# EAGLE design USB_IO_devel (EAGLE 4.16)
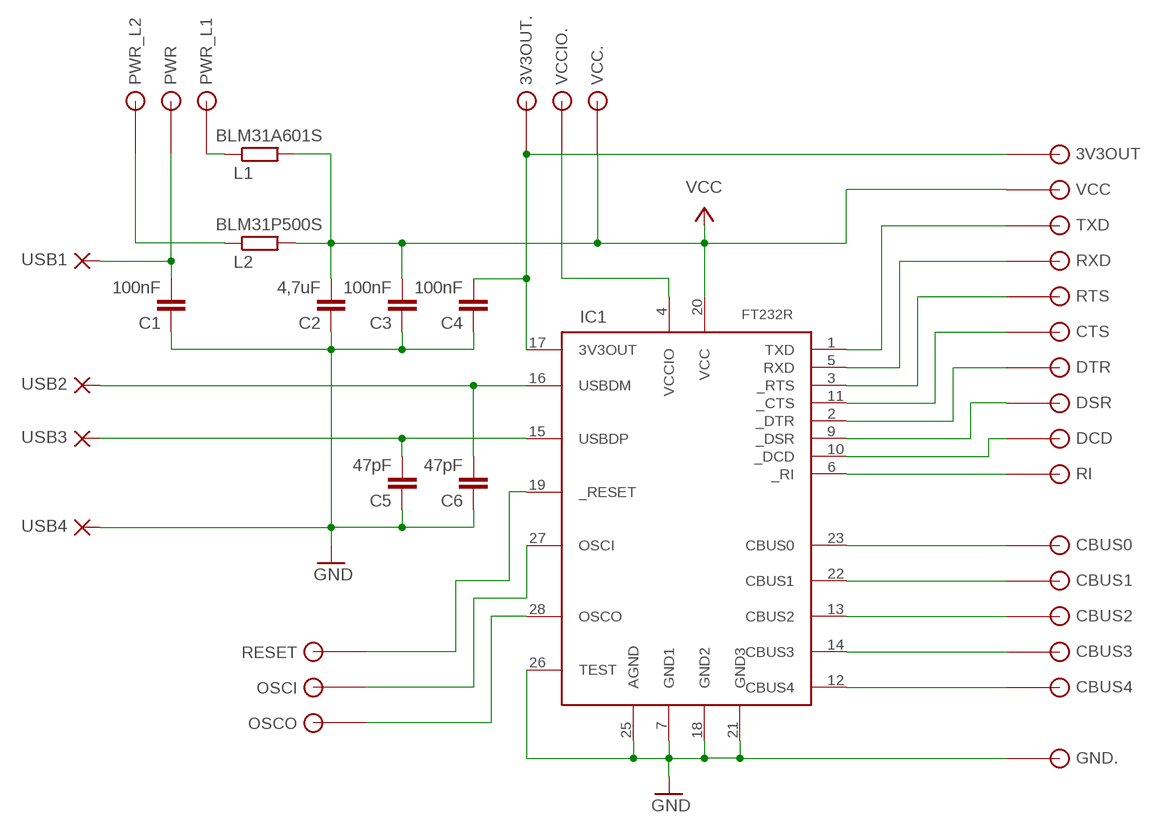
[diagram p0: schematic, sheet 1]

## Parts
3V3OUT  PADSQ254  [PADSQ254]
3V3OUT.  PADSQ254  [PADSQ254]
C1  100nF  C-EUC1206K  [C1206K]
C2  4,7uF  C-EUC1206K  [C1206K]
C3  100nF  C-EUC1206K  [C1206K]
C4  100nF  C-EUC1206K  [C1206K]
C5  47pF  C-EUC1206K  [C1206K]
C6  47pF  C-EUC1206K  [C1206K]
CBUS0  PADSQ254  [PADSQ254]
CBUS1  PADSQ254  [PADSQ254]
CBUS2  PADSQ254  [PADSQ254]
CBUS3  PADSQ254  [PADSQ254]
CBUS4  PADSQ254  [PADSQ254]
CTS  PADSQ254  [PADSQ254]
DCD  PADSQ254  [PADSQ254]
DSR  PADSQ254  [PADSQ254]
DTR  PADSQ254  [PADSQ254]
GND.  PADSQ254  [PADSQ254]
IC1  FT232RL  [SSOP28DB]
L1  BLM31A601S  R-EU_M1206  [M1206]
L2  BLM31P500S  R-EU_M1206  [M1206]
OSCI  PADSQ254  [PADSQ254]
OSCO  PADSQ254  [PADSQ254]
PWR  PADSQ254  [PADSQ254]
PWR_L1  PADSQ254  [PADSQ254]
PWR_L2  PADSQ254  [PADSQ254]
RESET  PADSQ254  [PADSQ254]
RI  PADSQ254  [PADSQ254]
RTS  PADSQ254  [PADSQ254]
RXD  PADSQ254  [PADSQ254]
TXD  PADSQ254  [PADSQ254]
USB1  2,54/0,8  [2,54/0,8]
USB2  2,54/0,8  [2,54/0,8]
USB3  2,54/0,8  [2,54/0,8]
USB4  2,54/0,8  [2,54/0,8]
VCC  PADSQ254  [PADSQ254]
VCC.  PADSQ254  [PADSQ254]
VCCIO.  PADSQ254  [PADSQ254]

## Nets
GND: C1.1 C2.1 C3.1 C4.1 C5.1 C6.1 GND..1 IC1.7(GND1) IC1.18(GND2) IC1.21(GND3) IC1.25(AGND) IC1.26(TEST) USB4.1(P)
N$1: C6.2 IC1.16(USBDM) USB2.1(P)
N$2: L1.1 PWR_L1.1
N$3: IC1.1(TXD) TXD.1
N$4: C5.2 IC1.15(USBDP) USB3.1(P)
N$5: 3V3OUT.1 3V3OUT..1 C4.2 IC1.17(3V3OUT)
N$6: IC1.5(RXD) RXD.1
N$7: IC1.3(_RTS) RTS.1
N$8: CTS.1 IC1.11(_CTS)
N$9: DTR.1 IC1.2(_DTR)
N$10: DSR.1 IC1.9(_DSR)
N$11: DCD.1 IC1.10(_DCD)
N$12: IC1.6(_RI) RI.1
N$13: CBUS0.1 IC1.23(CBUS0)
N$14: CBUS1.1 IC1.22(CBUS1)
N$15: CBUS2.1 IC1.13(CBUS2)
N$16: CBUS3.1 IC1.14(CBUS3)
N$17: CBUS4.1 IC1.12(CBUS4)
N$21: IC1.4(VCCIO) VCCIO..1
N$22: C1.2 PWR.1 USB1.1(P)
N$23: IC1.28(OSCO) OSCO.1
N$24: IC1.27(OSCI) OSCI.1
N$25: IC1.19(_RESET) RESET.1
N$31: L2.1 PWR_L2.1
VCC: C2.2 C3.2 IC1.20(VCC) L1.2 L2.2 VCC.1 VCC..1

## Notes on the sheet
- FT232R

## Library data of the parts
3V3OUT 3V3OUT. CBUS0 CBUS1-CBUS4 CTS DCD DSR DTR GND. OSCI OSCO PWR PWR_L1 PWR_L2 RESET RI RTS RXD TXD VCC VCC. VCCIO. = misc:PAD
C1-C6 = rcl:C-EU: CAPACITOR, European symbol
IC1 = ftdichip:FT232RL: USB UART 4th Generation USB UART (USB <-> Serial) Controller
L1 L2 = rcl:R-EU_: RESISTOR, European symbol
USB1-USB4 = wirepad:2,54/0,8: THROUGH-HOLE PAD

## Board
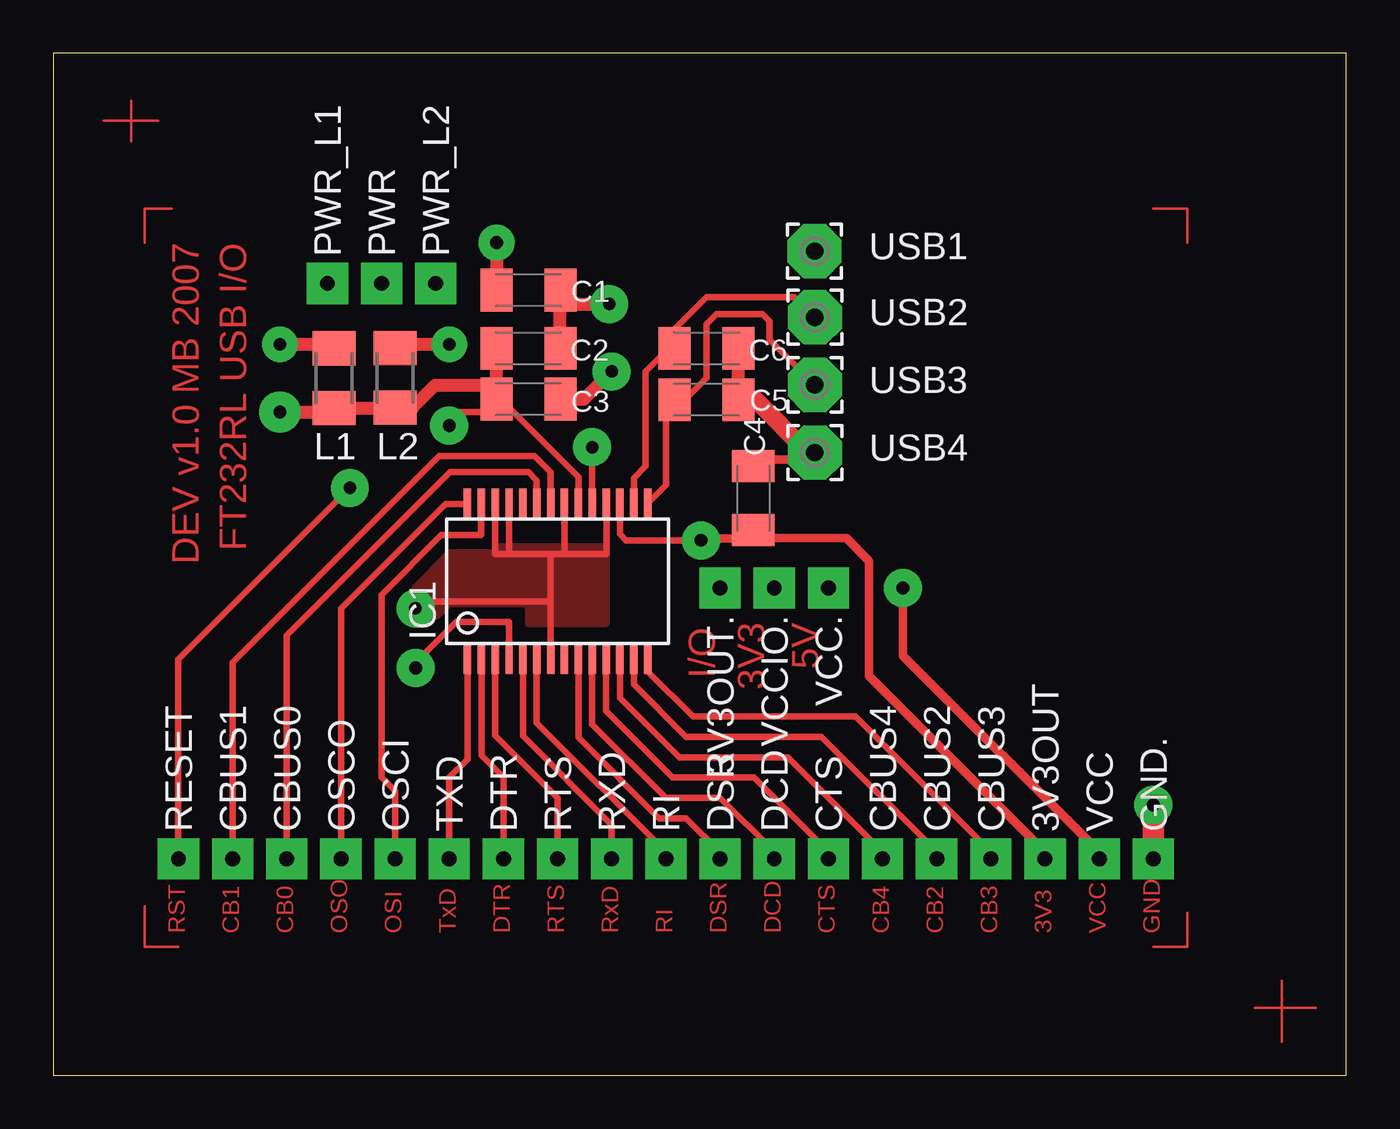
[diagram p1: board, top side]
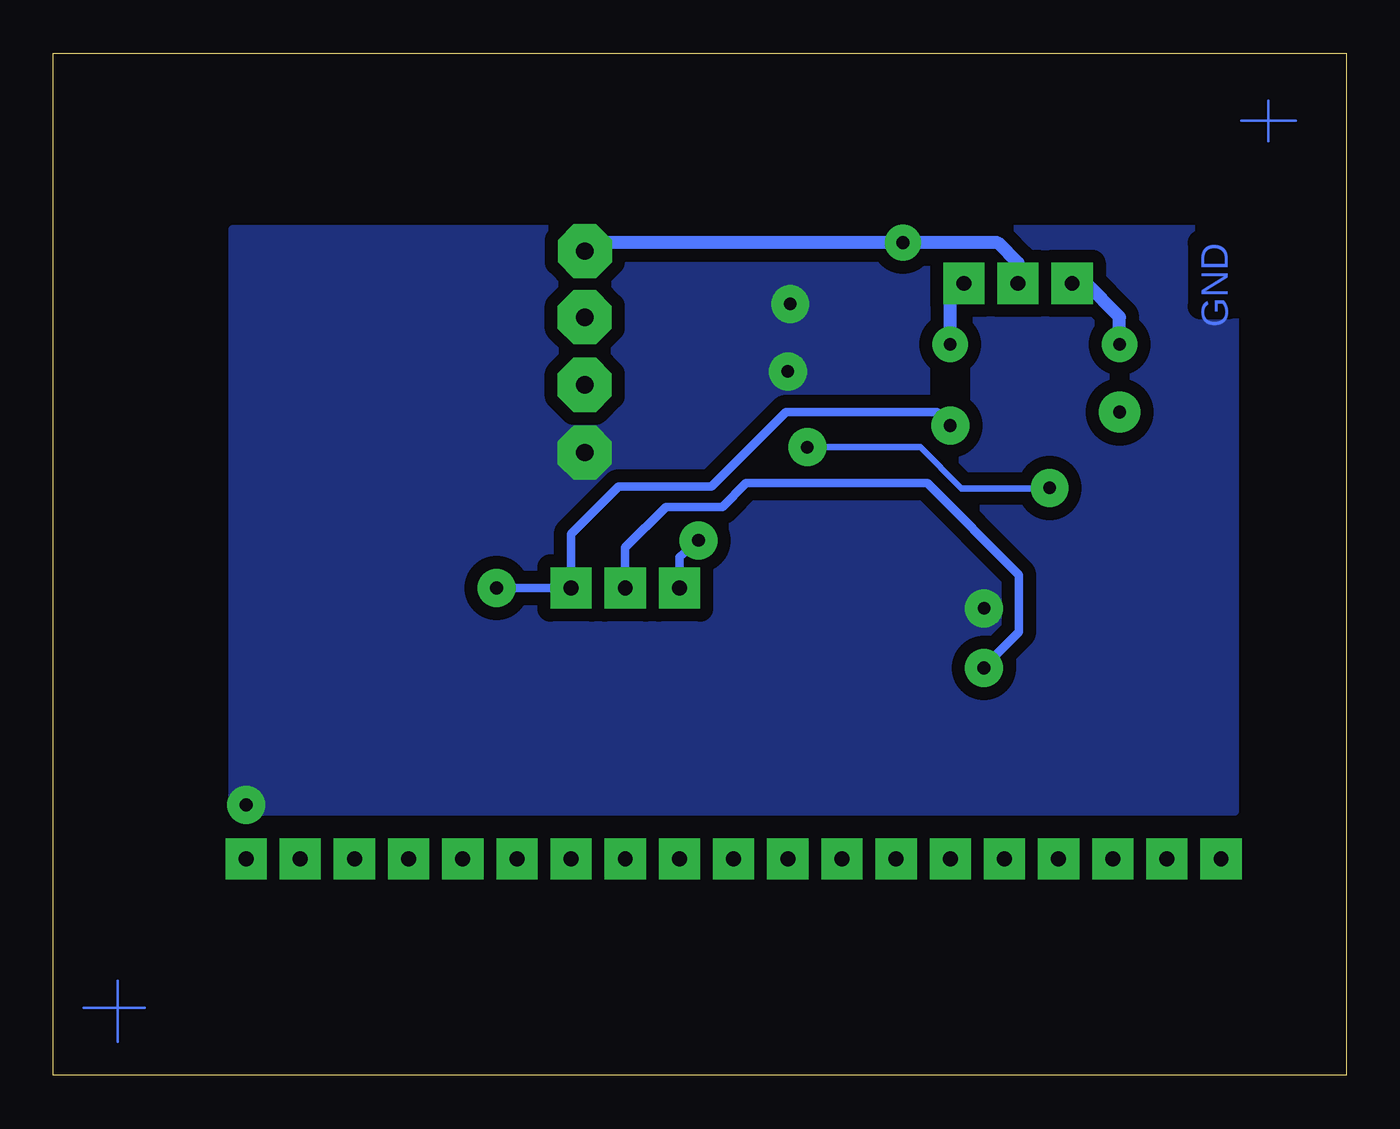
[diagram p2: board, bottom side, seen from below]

Size 60.63 x 47.93 mm. Coordinates in mm from the lower left corner, seen from the top.
Outline: 0,0 60.63,0 60.63,47.93 0,47.93 0,0
Copper layers (1*16): Top 0.035mm / dielectric 1.5mm / Bottom 0.035mm
Design rules "default": minimum track width 10mil, minimum drill 24mil, track to track 8mil, track to pad 8mil, pad to pad 8mil, via to via 8mil, smd to smd 8mil, copper to edge 40mil, drill to drill 8mil, minimum pad ring 10mil, minimum via ring 8mil, stop-mask expansion 4mil, vias tented up to drill 0mil, thermal gap 10mil
bRestrict: area 18.3,31.7 to 18.9,33

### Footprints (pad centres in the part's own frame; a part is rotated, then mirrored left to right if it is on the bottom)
PADSQ254 = drill 0.7 pad 1.93 square: 1 0,0
C1206K = smd 1.5 x 2: 1 -1.5,0; 2 1.5,0
SSOP28DB = smd 0.348 x 1.397: 1 -4.225,-3.656; 2 -3.575,-3.656; 3 -2.925,-3.656; 4 -2.275,-3.656; 5 -1.625,-3.656; 6 -0.975,-3.656; 7 -0.325,-3.656; 8 0.325,-3.656; 9 0.975,-3.656; 10 1.625,-3.656; 11 2.275,-3.656; 12 2.925,-3.656; 13 3.575,-3.656; 14 4.225,-3.656; 15 4.225,3.656; 16 3.575,3.656; 17 2.925,3.656; 18 2.275,3.656; 19 1.625,3.656; 20 0.975,3.656; 21 0.325,3.656; 22 -0.325,3.656; 23 -0.975,3.656; 24 -1.625,3.656; 25 -2.275,3.656; 26 -2.925,3.656; 27 -3.575,3.656; 28 -4.225,3.656
M1206 = smd 1.6 x 2: 1 -1.4,0; 2 1.4,0
2,54/0,8 = drill 0.813 pad 2.54 octagon: 1 0,0

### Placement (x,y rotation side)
3V3OUT  46.51,10.15 90 top
3V3OUT.  31.27,22.85 270 top
C1  22.28,36.83 180 top
C2  22.28,34.09 180 top
C3  22.28,31.71 180 top
C4  32.83,27.07 270 top
C5  30.63,31.68 180 top
C6  30.63,34.09 180 top
CBUS0  10.95,10.15 90 top
CBUS1  8.41,10.15 90 top
CBUS2  41.43,10.15 90 top
CBUS3  43.97,10.15 90 top
CBUS4  38.89,10.15 90 top
CTS  36.35,10.15 90 top
DCD  33.81,10.15 90 top
DSR  31.27,10.15 90 top
DTR  21.11,10.15 90 top
GND.  51.59,10.15 90 top
IC1  23.65,23.17 0 top
L1  13.17,32.7 270 top
L2  16.03,32.71 270 top
OSCI  16.03,10.15 90 top
OSCO  13.49,10.15 90 top
PWR  15.39,37.14 90 top
PWR_L1  12.85,37.14 90 top
PWR_L2  17.93,37.14 90 top
RESET  5.87,10.15 90 top
RI  28.73,10.15 90 top
RTS  23.65,10.15 90 top
RXD  26.19,10.15 90 top
TXD  18.57,10.15 90 top
USB1  35.7,38.65 270 top
USB2  35.71,35.55 270 top
USB3  35.71,32.38 270 top
USB4  35.71,29.2 270 top
VCC  49.05,10.15 90 top
VCC.  36.35,22.85 270 top
VCCIO.  33.81,22.85 270 top

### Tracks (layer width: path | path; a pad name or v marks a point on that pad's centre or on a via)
GND  (via drill 0.6 pad 1.78)
  Top 0.305: IC1.26 20.72,24.44 21.36,24.44 IC1.25 21.37,24.44 23.33,24.44 | 23.33,24.44 23.96,24.44 IC1.21 23.97,24.44 25.93,24.44 25.93,26.83 IC1.18 | 23.33,24.44 IC1.7 23.32,22.22 17.3,22.22 v16.98,21.9
  Top 0.406: USB4.1 35.71,28.89 33.15,28.89 C4.1
  Top 0.61: C1.1 23.78,36.51 23.77,36.51 23.77,36.18 | C2.1 23.77,36.18 | C6.1 32.13,31.83 32.22,31.74 32.16,31.68 C5.1 32.92,31.68 | USB4.1 35.39,29.2 | 23.77,36.18 v26.07,36.18 | C3.1 24.89,31.71 v26.19,33.02
  Top 0.813: 35.39,29.2 32.92,31.68 | USB4.1 35.53,29.08
  Top 1.016: GND..1 v51.59,12.68
  pour Bottom (isolate 0.61, no thermals): 5.23,12.38 52.22,12.38 52.22,39.68 5.23,39.68
  pour Top (isolate 0.305, no thermals): 20.79,24.76 25.9,24.76 25.9,21.2 22.3,21.2 22.3,22.14 18.53,22.14 17.96,21.57 16.98,21.57 16.98,22.84 18.62,24.48 20.73,24.48
N$1
  Top 0.305: IC1.16 27.22,28.02 27.78,28.57 27.78,33.02 28.85,34.09 C6.2 29.13,35.01 30.63,36.51 34.76,36.51 USB2.1
N$2  (via drill 0.6 pad 1.68)
  Top 0.61: L1.1 13.17,34.28 v10.63,34.28
  Bottom 0.61: PWR_L1.1 12.22,37.14 10.63,35.56 v10.63,34.28
N$3
  Top 0.305: IC1.1 19.42,14.82 18.57,13.97 TXD.1
N$4
  Top 0.305: IC1.15 28.73,27.68 28.73,31.43 28.88,31.43 C5.2 29.62,31.68 30.63,32.7 30.63,35.24 31.1,35.71 33.25,35.71 33.58,35.38 33.58,34.51 USB3.1
N$5  (via drill 0.6 pad 1.78)
  Top 0.305: IC1.17 26.57,25.39 26.57,25.38 26.86,25.09 30.37,25.09 | v30.38,25.09 30.39,25.09
  Top 0.406: 3V3OUT.1 46.51,10.47 38.25,18.73 38.25,24.13 37.19,25.19 33.06,25.19 32.86,25.55 C4.2 32.54,25.18 30.45,25.18 30.37,25.09 v30.38,25.09
  Bottom 0.406: v30.38,25.09 31.27,24.32 3V3OUT..1
N$6
  Top 0.305: IC1.5 22.02,15.91 26.19,11.74 RXD.1
N$7
  Top 0.305: IC1.3 20.72,15.94 23.65,13.01 RTS.1
N$8
  Top 0.305: IC1.11 25.92,17.09 29.04,13.97 32.86,13.97 36.35,10.47 CTS.1
N$9
  Top 0.305: IC1.2 20.07,15 21.11,13.97 DTR.1
N$10
  Top 0.305: IC1.9 24.62,15.85 28.41,12.06 29.68,12.06 31.27,10.47 DSR.1
N$11
  Top 0.305: IC1.10 25.27,16.47 28.73,13.01 31.27,13.01 33.81,10.47 DCD.1
N$12
  Top 0.305: IC1.6 22.67,16.53 28.73,10.47 RI.1
N$13
  Top 0.305: IC1.23 22.67,27.91 22.28,28.3 18.62,28.3 10.95,20.63 CBUS0.1
N$14
  Top 0.305: IC1.22 23.32,28.29 22.57,29.04 18.08,29.04 8.41,19.36 CBUS1.1
N$15
  Top 0.305: IC1.13 27.22,18.33 29.68,15.87 36.03,15.87 41.43,10.47 CBUS2.1
N$16
  Top 0.305: IC1.14 27.87,18.95 30,16.82 37.62,16.82 43.97,10.47 CBUS3.1
N$17
  Top 0.305: IC1.12 26.57,17.71 29.36,14.92 34.44,14.92 38.89,10.47 CBUS4.1
N$18
  Top 0.127: 2.37,44.76 4.92,44.76
N$19
  Top 0.127: 3.64,45.71 3.64,43.81
N$20
  Top 0.127: 57.62,1.58 57.62,4.44
N$21  (via drill 0.6 pad 1.78)
  Top 0.305: IC1.4 21.37,21.27 18.89,21.27 16.98,19.36 16.98,19.05 16.99,19.06 v16.99,19.11
  Bottom 0.406: VCCIO..1 33.81,24.76 31.9,26.67 29.25,26.67 28.14,27.77 19.65,27.77 15.35,23.48 15.35,20.78 17.02,19.12 v17.01,19.11 v16.99,19.11
N$22  (via drill 0.6 pad 1.68)
  Top 0.61: 20.79,36.82 20.79,36.83 C1.2 20.79,36.82 | v20.79,39.05 20.79,36.82
  Bottom 0.61: USB1.1 35.31,39.05 v20.79,39.05 16.35,39.05 15.39,38.09 PWR.1
N$23
  Top 0.305: OSCO.1 13.49,21.9 18.39,26.8 19.41,26.8 19.41,26.81 IC1.28
N$24
  Top 0.305: OSCI.1 16.03,13.33 15.39,13.97 15.39,22.54 18.19,25.33 20.07,25.33 IC1.27 | IC1.27 | IC1.27
N$25  (via drill 0.6 pad 1.78)
  Top 0.305: IC1.19 25.27,28.62 v25.27,29.46 | v13.91,27.55 5.87,19.51 RESET.1
  Bottom 0.305: v25.27,29.46 19.96,29.46 18.03,27.53 13.89,27.53 13.89,27.54 v13.91,27.55
N$26
  Top 0.127: 56.35,3.17 59.21,3.17
N$27
  Bottom 0.127: 2.37,44.76 4.92,44.76
N$28
  Bottom 0.127: 3.64,45.71 3.64,43.81
N$29
  Bottom 0.127: 56.35,3.17 59.21,3.17
N$30
  Bottom 0.127: 57.62,1.58 57.62,4.44
N$31  (via drill 0.6 pad 1.68)
  Top 0.61: L2.1 16.03,34.28 v18.57,34.28
  Bottom 0.61: PWR_L2.1 18.57,36.51 v18.57,34.28
N$32
  Top 0.127: 4.28,39.05 4.28,40.63 5.55,40.63
N$33
  Top 0.127: 4.28,7.93 4.28,6.03 5.87,6.03
N$34
  Top 0.127: 51.59,6.03 53.18,6.03 53.18,7.61
N$35
  Top 0.127: 51.59,40.63 53.18,40.63 53.18,39.05
N$36  (via drill 0.6 pad 1.93)
  Top 0.61: v10.63,31.11 13.17,31.11
VCC  (via drill 0.6 pad 1.78)
  Top 0.305: IC1.20 24.62,28.05 21.11,31.57 20.79,31.72 | C3.2 20.81,31.11 18.89,31.11 v18.57,30.48
  Top 0.406: VCC.1 49.05,10.47 39.84,19.68 v39.84,22.85
  Top 0.61: C3.2 20.79,31.72 20.79,32.37 | 20.79,32.37 20.79,34.09 C2.2 20.66,33.97 | L2.2 16.03,31.43 | L1.2 16.03,31.3 L2.2 | L2.2 16.85,31.31 17.91,32.37 20.79,32.37
  Bottom 0.406: v39.84,22.85 VCC..1 36.35,25.39 34.13,27.62 29.77,27.62 26.28,31.11 19.2,31.11 v18.57,30.48

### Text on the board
Top: DEV v1.0 MB 2007 | FT232RL USB I/O | 3V3 | 5V | I/O | RST | CB1 | CB0 | OSO | OSI | TxD | DTR | RTS | RxD | RI | DSR | DCD | CTS | CB4 | CB2 | CB3 | 3V3 | VCC | GND
Bottom: GND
